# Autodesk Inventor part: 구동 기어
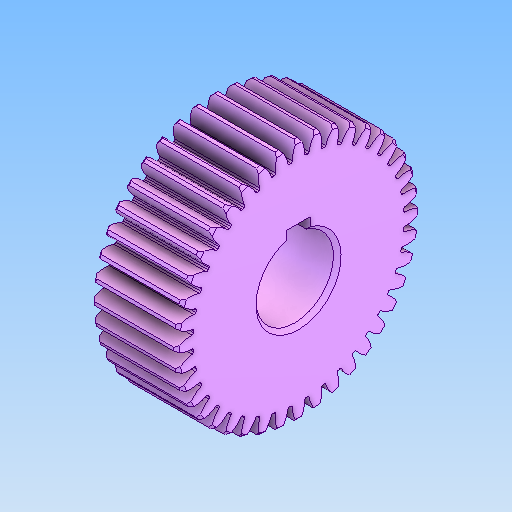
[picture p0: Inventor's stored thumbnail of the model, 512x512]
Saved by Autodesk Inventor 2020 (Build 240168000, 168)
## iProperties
Created: 2025-11
Part Number: 구동 기어
Material: 강철, 합금
Document SubType Name: Modeling
Designer: PC2-06
Density: 7.73 g/cm^3
Appearance: 기본값
Author: jhkim
Sending System: Autodesk Inventor 2026
Preprocessor: ST-DEVELOPER v20.1
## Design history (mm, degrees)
feature "솔리드1"
node "솔리드2"
